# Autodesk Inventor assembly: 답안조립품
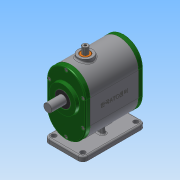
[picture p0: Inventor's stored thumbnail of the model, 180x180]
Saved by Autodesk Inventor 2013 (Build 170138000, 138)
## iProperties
Created: 2016-12
Part Number: 답안조립품
Document SubType Name: Assembly
Designer: Administrator
Mass: 2543.94 g
Surface Area: 2007.05 cm^2
Volume: 724.781 cm^3
Density: 3.50995 g/cm^3
Author: Administrator
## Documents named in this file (14)
- C:\Users\Administrator\Desktop\361208V1029\답안조립품.iam
- C:\Users\Administrator\Desktop\361208V1029\본체.ipt
- C:\Users\Administrator\Desktop\361208V1029\가변스프링.ipt
- C:\Users\Administrator\Desktop\361208V1029\뒤커버.ipt
- C:\Users\Administrator\Desktop\361208V1029\메인축.ipt
- C:\Users\Administrator\Desktop\361208V1029\베어링 608.ipt
- C:\Users\Administrator\Desktop\361208V1029\베어링 6003.ipt
- C:\Users\Administrator\Desktop\361208V1029\볼트 M4.ipt
- C:\Users\Administrator\Desktop\361208V1029\부시.ipt
- C:\Users\Administrator\Desktop\361208V1029\서브축.ipt
- C:\Users\Administrator\Desktop\361208V1029\슬라이더.ipt
- C:\Users\Administrator\Desktop\361208V1029\앞커버.ipt
- C:\Users\Administrator\Desktop\361208V1029\오일실 8 22 7.ipt
- C:\Users\Administrator\Desktop\361208V1029\오일실 17 32 8.ipt
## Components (1 placed, 1 different names)
1. 가변스프링:1
